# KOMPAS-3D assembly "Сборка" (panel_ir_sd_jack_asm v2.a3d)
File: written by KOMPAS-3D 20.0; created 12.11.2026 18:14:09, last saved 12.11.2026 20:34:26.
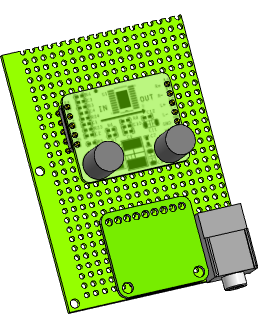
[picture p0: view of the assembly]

Document properties: Полное имя файла: D:\myProjects\Progect_esp32\box_compas\сборки компонентов\panel_ir_sd_jack_asm v2.a3d

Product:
- Part/product: Сборка
    Масса: 0.0721258
  - Component [detail]: Деталь  | Масса: 0.0310587; source file: ..\макетки\Макетная плата_04.m3d
  - Component [detail]: Деталь  | Масса: 0.0145596; source file: ..\разъемы\PJ-306BM.m3d
  - Component [detail]: Деталь  | Масса: 0.0074136; source file: ..\SD card\Adafruit_Micro_SD_SPI_or_SDIO.m3d
  - Component [assembly]: Сборка  | Масса: 0.0190939; source file: ..\усилитель\HT8698_asm.a3d

Referenced files in D:\myProjects\Progect_esp32\box_compas\макетки\: Макетная плата_04.m3d
Referenced files in D:\myProjects\Progect_esp32\box_compas\разъемы\: PJ-306BM.m3d
Referenced files in D:\myProjects\Progect_esp32\box_compas\SD card\: Adafruit_Micro_SD_SPI_or_SDIO.m3d
Referenced files in D:\myProjects\Progect_esp32\box_compas\усилитель\: HT8698_asm.a3d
